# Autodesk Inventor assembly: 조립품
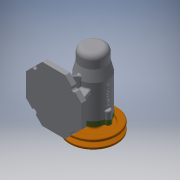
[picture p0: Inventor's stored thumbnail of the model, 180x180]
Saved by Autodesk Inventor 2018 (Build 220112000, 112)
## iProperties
Created: 2019-12
Part Number: 조립품
Document SubType Name: Assembly
Designer: Administrator
Author: Administrator
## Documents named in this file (12)
- C:\Users\Administrator\Desktop\491204V1065\조립품.iam
- C:\Users\Administrator\Desktop\491204V1065\본체.ipt
- C:\Users\Administrator\Desktop\491204V1065\축.ipt
- C:\Users\Administrator\Desktop\491204V1065\베어링 6004.ipt
- C:\Users\Administrator\Desktop\491204V1065\키 5 x 5 x 16.ipt
- C:\Users\Administrator\Desktop\491204V1065\V벨트풀리.ipt
- C:\Users\Administrator\Desktop\491204V1065\어댑터슬리브.ipt
- C:\Users\Administrator\Desktop\491204V1065\볼트 M4.ipt
- C:\Users\Administrator\Desktop\491204V1065\베어링 51202.ipt
- C:\Users\Administrator\Desktop\491204V1065\커버.ipt
- C:\Users\Administrator\Desktop\491204V1065\오일 실.ipt
- C:\Users\Administrator\Desktop\491204V1065\멈춤나사 M3.ipt
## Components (1 placed, 1 different names)
1. V벨트풀리:1
